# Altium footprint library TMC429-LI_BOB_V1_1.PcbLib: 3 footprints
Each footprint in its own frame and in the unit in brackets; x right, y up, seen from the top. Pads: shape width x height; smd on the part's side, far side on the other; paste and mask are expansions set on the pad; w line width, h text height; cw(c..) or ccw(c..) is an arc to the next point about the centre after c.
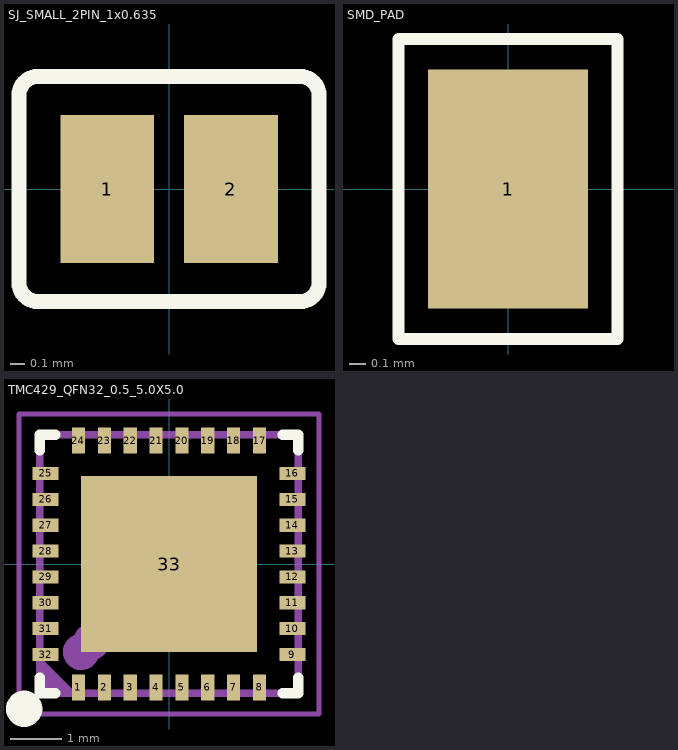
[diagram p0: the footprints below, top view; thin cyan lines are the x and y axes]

## SJ_SMALL_2PIN_1x0.635 [mm]
pads (2):
  rect 0.635x1 smd: 1(-0.419,0) 2(0.419,0)
Top Overlay:
  lines w0.102: -1.016,-0.635 ccw(c-0.889,-0.635) -0.889,-0.762 0.889,-0.762 ccw(c0.889,-0.635) 1.016,-0.635 1.016,0.635 ccw(c0.889,0.635) 0.889,0.762 -0.889,0.762 ccw(c-0.889,0.635) -1.016,0.635 -1.016,-0.635

## SMD_PAD [mm]
pads (1):
  rect 1x1.5 smd: 1(0,0)
Top Overlay:
  lines w0.076: -0.686,-0.94 0.686,-0.94 0.686,0.94 -0.686,0.94 -0.686,-0.94

## TMC429_QFN32_0.5_5.0X5.0 [mm]
pads (33):
  rect 0.254x0.5 smd: 1(-1.75,-2.385) 2(-1.25,-2.385) 3(-0.75,-2.385) 4(-0.25,-2.385) 5(0.25,-2.385) 6(0.75,-2.385) 7(1.25,-2.385) 8(1.75,-2.385) 17(1.75,2.385) 18(1.25,2.385) 19(0.75,2.385) 20(0.25,2.385) 21(-0.25,2.385) 22(-0.75,2.385) 23(-1.25,2.385) 24(-1.75,2.385)
  rect 0.5x0.254 smd: 9(2.385,-1.75) 10(2.385,-1.25) 11(2.385,-0.75) 12(2.385,-0.25) 13(2.385,0.25) 14(2.385,0.75) 15(2.385,1.25) 16(2.385,1.75) 25(-2.385,1.75) 26(-2.385,1.25) 27(-2.385,0.75) 28(-2.385,0.25) 29(-2.385,-0.25) 30(-2.385,-0.75) 31(-2.385,-1.25) 32(-2.385,-1.75)
  rect 3.4x3.4 smd paste-25.4: 33(0,0)
Top Overlay:
  circle w0.5: c-2.8,-2.8 r0.1
  lines w0.2: -2.5,-2.2 -2.5,-2.5 -2.2,-2.5 ; -2.5,2.2 -2.5,2.5 -2.2,2.5 ; 2.2,-2.5 2.5,-2.5 2.5,-2.2 ; 2.2,2.5 2.5,2.5 2.5,2.2
Top Paste:
  region: 0.254,1.524 1.524,1.524 1.524,0.254 0.254,0.254
  region: -1.524,1.524 -0.254,1.524 -0.254,0.254 -1.524,0.254
  region: -1.524,-0.254 -0.254,-0.254 -0.254,-1.524 -1.524,-1.524
  region: 0.254,-0.254 1.524,-0.254 1.524,-1.524 0.254,-1.524
Mechanical 13:
  circle w0.5: c-1.7,-1.7 r0.1
  lines w0.15: -2.5,-2.5 2.5,-2.5 2.5,2.5 -2.5,2.5 -2.5,-2.5
Mechanical 15:
  lines w0.1: -2.9,-2.9 2.9,-2.9 2.9,2.9 -2.9,2.9 -2.9,-2.9
TopAsm:
  circle w0.5: c-1.5,-1.5 r0.1
  region: -2.5,-1.794 -1.794,-2.5 -2.5,-2.5
  lines w0.076: -2.5,-2.5 2.5,-2.5 2.5,2.5 -2.5,2.5 -2.5,-2.5
  text ".Designator" at -2,-0.5 h1.27
3D body: height 0.9, standoff 0, extent -2.5,-2.5 2.5,2.5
